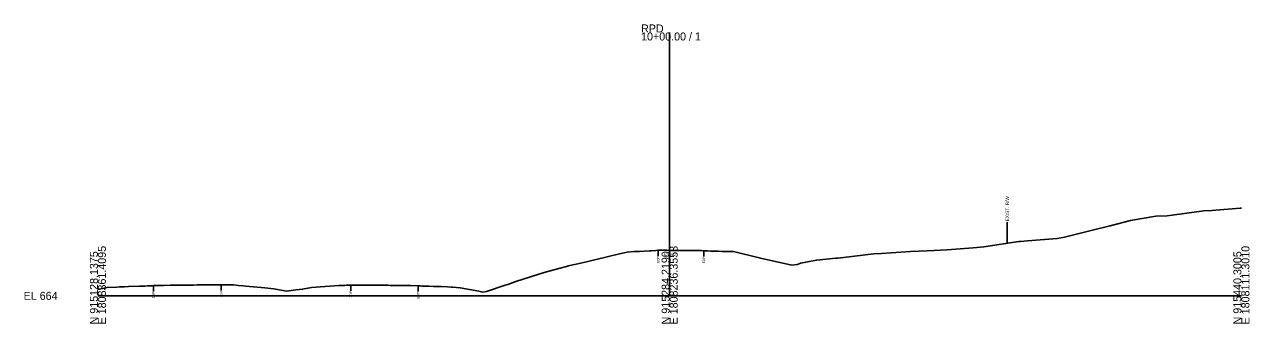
# Model space of a CAD drawing. Extents: x -26 to 403, y -10 to 8517.
# Drawn here: x -25.7 to 402.8, y -9.7 to 95 of the extents above; entities that cross this region are included whole.
import ezdxf

# ---------------------------------------------------------------- set-up
doc = ezdxf.new("R2010")
doc.units = 0
for name, color, linetype in [('Exist Cross Section Cell', 7, 'Continuous'), ('Exist XS Center Line Elevation Label', 7, 'Continuous'), ('Exist XS Ground Line', 7, 'Continuous'), ('Old_Level_10', 7, 'Continuous')]:
    doc.layers.add(name, color=color, linetype=linetype)

msp = doc.modelspace()

# ---------------------------------------------------------------- linework, layer by layer
at = {"layer": 'Exist Cross Section Cell'}
for p, q in [((200, 0), (200, 92.2)), ((0, 0), (200, 0)), ((200, 0), (400, 0))]:
    msp.add_line(p, q, dxfattribs=at)
at = {"layer": 'Exist XS Ground Line'}
msp.add_lwpolyline([(0, 2.2), (3.26, 2.91), (6.61, 3.08), (7.57, 3.12), (9.25, 3.18), (10.73, 3.24), (14.56, 3.4), (15.04, 3.42), (16.41, 3.42), (17.37, 3.45), (18.91, 3.53), (19.39, 3.6), (20, 3.61), (21.41, 3.64), (22.89, 3.66), (25.39, 3.7), (26.07, 3.71), (28.93, 3.73), (29.31, 3.73), (31.27, 3.76), (32.61, 3.78), (33.37, 3.79), (34.66, 3.81), (35.65, 3.82), (37.37, 3.84), (38.2, 3.84), (38.87, 3.85), (40.01, 3.85), (41.41, 3.87), (42.02, 3.88), (43.15, 3.89), (45.38, 3.8), (47.4, 3.8), (49.19, 3.62), (50.82, 3.47), (51.77, 3.37), (58.42, 2.85), (61.56, 2.42), (65.93, 1.69), (69.2, 2.07), (71.57, 2.3), (74.71, 2.93), (84.3, 3.65), (84.98, 3.66), (86.23, 3.67), (86.92, 3.71), (88.43, 3.79), (89.79, 3.78), (90.1, 3.78), (93.34, 3.76), (95.13, 3.75), (96.56, 3.73), (97.36, 3.73), (99.92, 3.7), (100.41, 3.69), (101.07, 3.69), (101.38, 3.68), (102.24, 3.67), (102.93, 3.66), (105.35, 3.63), (105.79, 3.62), (106.14, 3.62), (107.56, 3.6), (109.38, 3.56), (112.03, 3.53), (112.67, 3.49), (113.36, 3.44), (115.75, 3.33), (117.34, 3.29), (118.97, 3.25), (120.02, 3.23), (122.28, 3.16), (123.51, 3.05), (124.2, 2.99), (126.77, 2.8), (133.24, 1.6), (134.69, 1.32), (135.92, 1.56), (142.49, 3.76), (143.34, 3.95), (146.19, 4.97), (156.15, 8.16), (161.19, 9.57), (163.87, 10.31), (164.57, 10.52), (165.13, 10.63), (168.97, 11.48), (178.18, 13.7), (182.49, 14.71), (185.14, 15.33), (187.53, 15.47), (188.74, 15.52), (189.43, 15.56), (192.89, 15.73), (193.66, 15.76), (195.2, 15.9), (195.98, 15.95), (197.32, 15.94), (198.29, 15.94), (199.05, 15.93), (200, 15.92), (201.33, 15.91), (201.85, 15.9), (202.26, 15.9), (203.74, 15.9), (205.46, 15.88), (206.02, 15.87), (208.66, 15.85), (209.31, 15.84), (211.15, 15.82), (211.98, 15.81), (213.29, 15.73), (214.27, 15.66), (215.32, 15.62), (216.19, 15.59), (217.1, 15.58), (218.29, 15.56), (222.37, 15.5), (231.79, 13.21), (242.7, 10.74), (244.71, 10.97), (245.82, 11.43), (248.89, 12.05), (251.32, 12.51), (258.14, 13.16), (258.66, 13.21), (260.76, 13.45), (271.48, 14.66), (274.14, 14.85), (284.29, 15.52), (290.13, 15.8), (297.1, 16.11), (306.12, 16.82), (309.92, 17.2), (322.12, 18.99), (322.73, 19.06), (325.22, 19.27), (335.55, 20.09), (338.11, 20.53), (348.36, 23.07), (354.1, 24.51), (361.17, 26.39), (370.09, 27.92), (373.99, 28.03), (386.09, 29.62), (386.8, 29.72), (389.68, 29.93), (399.61, 30.71), (400, 30.73)], dxfattribs=at)
at = {"layer": 'Old_Level_10'}
for p, q in [((318.12, 25.8), (318.12, 18.4)), ((195.98, 15.95), (195.98, 13.9)), ((211.98, 15.81), (211.98, 13.76)), ((19.39, 3.6), (19.39, 1.55)), ((43.15, 3.89), (43.15, 1.84)), ((88.43, 3.79), (88.43, 1.74)), ((112.03, 3.53), (112.03, 1.48))]:
    msp.add_line(p, q, dxfattribs=at)

# ---------------------------------------------------------------- texts
at = {"layer": 'Exist Cross Section Cell'}
for s, p in [('RPD', (190, 92.2)), ('10+00.00 / 1', (190, 89.4)), ('EL 664', (-26, -1.4))]:
    msp.add_text(s, height=2.8, dxfattribs=at).set_placement(p)
for s, p in [('E 1808361.4095', (2.8, -10)), ('E 1808236.3553', (202.8, -10)), ('E 1808111.3010', (402.8, -10)), ('N 915128.1375', (0, -10)), ('N 915284.2190', (200, -10)), ('N 915440.3005', (400, -10))]:
    msp.add_text(s, height=2.8, rotation=90, dxfattribs=at).set_placement(p)
at = {"layer": 'Exist XS Center Line Elevation Label'}
msp.add_text('679.92', height=1, dxfattribs=at).set_placement((197.89, 13.92))
at = {"layer": 'Old_Level_10'}
for s, height, p in [('EXIST. R/W', 1.181, (318.71, 26.1)), ('EOP', 0.787, (196.37, 11.5)), ('EOP', 0.787, (212.37, 11.37)), ('EOP', 0.787, (19.79, -0.85)), ('EOP', 0.787, (43.55, -0.55)), ('EOP', 0.787, (88.82, -0.66)), ('EOP', 0.787, (112.42, -0.92))]:
    msp.add_text(s, height=height, rotation=90, dxfattribs=at).set_placement(p)

doc.saveas('drawing.dxf')
